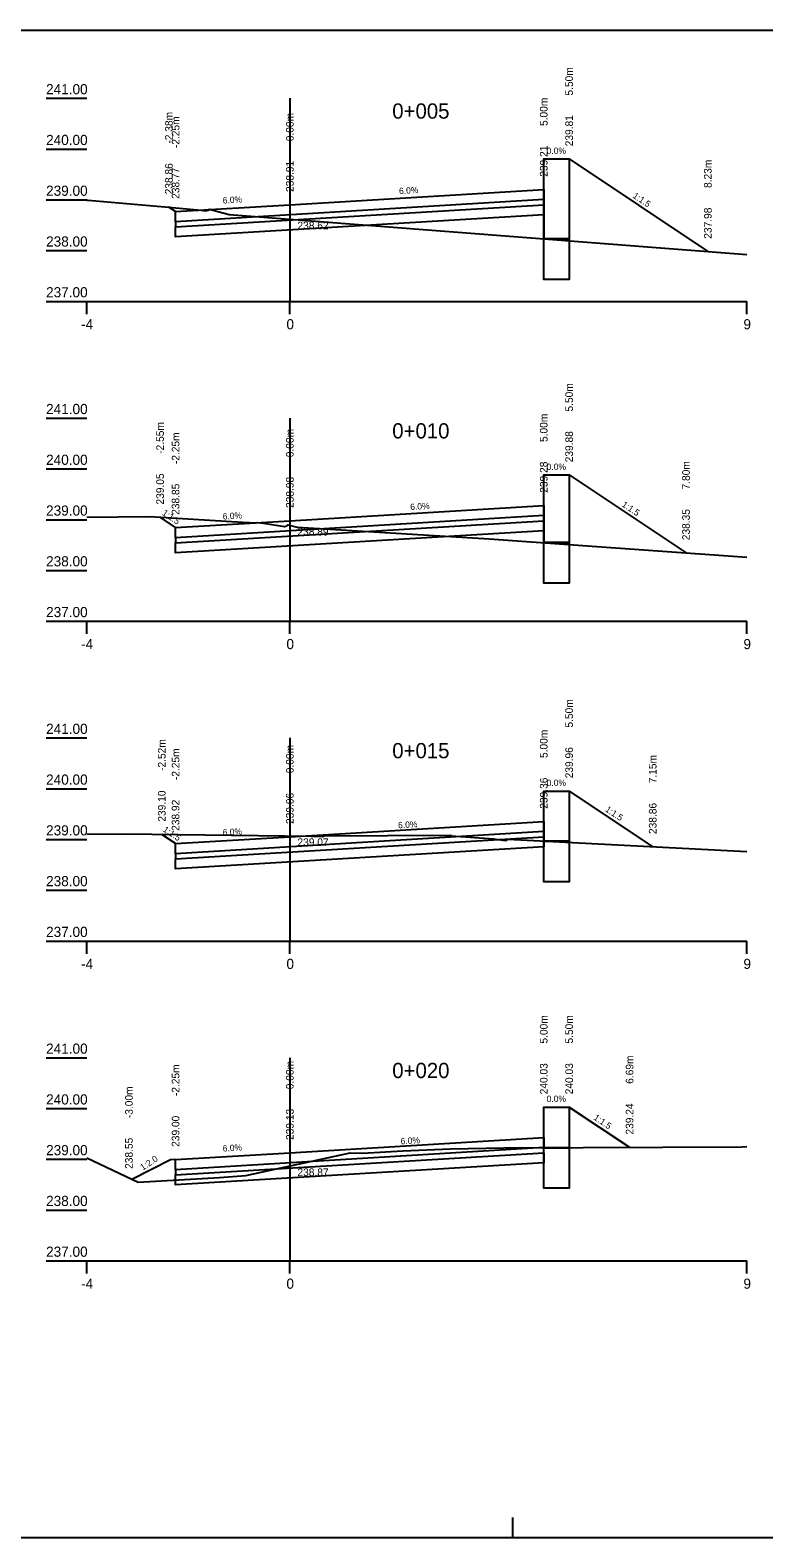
# Model space of a CAD drawing. Extents: x -578374 to -578229, y -1159997 to -1159967.
# Drawn here: x -578259.43 to -578244.98, y -1159996.88 to -1159967.18 of the extents above; entities that cross this region are included whole.
import ezdxf

# ---------------------------------------------------------------- set-up
doc = ezdxf.new("R2010")
doc.units = 0
for name, color, linetype in [('16', 7, 'Continuous'), ('21', 7, 'Continuous'), ('28', 7, 'Continuous'), ('59', 7, 'Continuous'), ('Body pricny rez', 7, 'Continuous'), ('Popis pricneho profilu', 7, 'Continuous'), ('Rámy', 7, 'Continuous')]:
    doc.layers.add(name, color=color, linetype=linetype)

msp = doc.modelspace()

# ---------------------------------------------------------------- linework, layer by layer
for points in [[(-578249.319, -1159970.321), (-578249.319, -1159969.721), (-578248.819, -1159969.721), (-578248.819, -1159971.292), (-578249.319, -1159971.292)], [(-578254.319, -1159970.621), (-578249.319, -1159970.321), (-578249.319, -1159970.521), (-578256.569, -1159970.956), (-578256.569, -1159970.756)], [(-578256.569, -1159970.956), (-578256.569, -1159971.057), (-578249.319, -1159970.622), (-578249.319, -1159970.521)], [(-578249.319, -1159970.622), (-578249.319, -1159970.822), (-578256.569, -1159971.257), (-578256.569, -1159971.057)], [(-578249.319, -1159971.292), (-578248.819, -1159971.292), (-578248.819, -1159972.092), (-578249.319, -1159972.092)], [(-578249.319, -1159976.546), (-578249.319, -1159975.946), (-578248.819, -1159975.946), (-578248.819, -1159977.279), (-578249.319, -1159977.279)], [(-578254.319, -1159976.846), (-578249.319, -1159976.546), (-578249.319, -1159976.746), (-578256.569, -1159977.181), (-578256.569, -1159976.981)], [(-578256.569, -1159977.181), (-578256.569, -1159977.282), (-578249.319, -1159976.847), (-578249.319, -1159976.746)], [(-578249.319, -1159976.847), (-578249.319, -1159977.047), (-578256.569, -1159977.482), (-578256.569, -1159977.282)], [(-578249.319, -1159977.279), (-578248.819, -1159977.279), (-578248.819, -1159978.079), (-578249.319, -1159978.079)], [(-578249.319, -1159982.771), (-578249.319, -1159982.171), (-578248.819, -1159982.171), (-578248.819, -1159983.159), (-578249.319, -1159983.159)], [(-578254.319, -1159983.071), (-578249.319, -1159982.771), (-578249.319, -1159982.971), (-578256.569, -1159983.406), (-578256.569, -1159983.206)], [(-578256.569, -1159983.406), (-578256.569, -1159983.507), (-578249.319, -1159983.072), (-578249.319, -1159982.971)], [(-578249.319, -1159983.072), (-578249.319, -1159983.272), (-578256.569, -1159983.707), (-578256.569, -1159983.507)], [(-578249.319, -1159983.159), (-578248.819, -1159983.159), (-578248.819, -1159983.959), (-578249.319, -1159983.959)], [(-578249.319, -1159988.996), (-578249.319, -1159988.396), (-578248.819, -1159988.396), (-578248.819, -1159989.198), (-578249.319, -1159989.198)], [(-578254.319, -1159989.296), (-578249.319, -1159988.996), (-578249.319, -1159989.196), (-578256.569, -1159989.631), (-578256.569, -1159989.431)], [(-578256.569, -1159989.631), (-578256.569, -1159989.732), (-578249.319, -1159989.297), (-578249.319, -1159989.196)], [(-578249.319, -1159989.297), (-578249.319, -1159989.497), (-578256.569, -1159989.932), (-578256.569, -1159989.732)], [(-578249.319, -1159989.198), (-578248.819, -1159989.198), (-578248.819, -1159989.998), (-578249.319, -1159989.998)]]:
    msp.add_lwpolyline(points, close=True)
for points in [[(-578248.819, -1159969.721), (-578246.088, -1159971.542)], [(-578249.319, -1159970.321), (-578249.319, -1159971.292)], [(-578258.319, -1159970.531), (-578258.289, -1159970.533), (-578256.779, -1159970.661), (-578256.063, -1159970.727), (-578255.975, -1159970.744), (-578255.918, -1159970.727), (-578255.905, -1159970.71), (-578255.515, -1159970.814), (-578245.319, -1159971.601)], [(-578256.569, -1159970.756), (-578256.701, -1159970.668)], [(-578248.819, -1159971.292), (-578248.819, -1159971.292), (-578248.819, -1159971.292), (-578248.819, -1159971.293), (-578248.819, -1159971.292), (-578248.818, -1159971.293), (-578248.819, -1159971.292), (-578248.818, -1159971.292)], [(-578249.319, -1159972.092), (-578249.319, -1159972.092), (-578249.319, -1159972.092), (-578249.319, -1159972.093), (-578249.319, -1159972.092), (-578249.318, -1159972.093), (-578249.319, -1159972.092), (-578249.318, -1159972.092)], [(-578248.819, -1159972.092), (-578248.819, -1159972.092), (-578248.819, -1159972.092), (-578248.819, -1159972.093), (-578248.819, -1159972.092), (-578248.818, -1159972.093), (-578248.819, -1159972.092), (-578248.818, -1159972.092)], [(-578248.819, -1159975.946), (-578246.517, -1159977.481)], [(-578249.319, -1159976.546), (-578249.319, -1159977.279)], [(-578258.319, -1159976.774), (-578257.073, -1159976.766), (-578255.248, -1159976.875), (-578254.979, -1159976.889), (-578254.955, -1159976.881), (-578254.838, -1159976.893), (-578254.424, -1159976.962), (-578254.379, -1159976.949), (-578254.36, -1159976.928), (-578254.177, -1159976.971), (-578250.394, -1159977.201), (-578245.319, -1159977.567)], [(-578256.569, -1159976.981), (-578256.874, -1159976.778)], [(-578248.819, -1159977.279), (-578248.819, -1159977.278), (-578248.819, -1159977.279), (-578248.819, -1159977.279), (-578248.819, -1159977.279), (-578248.818, -1159977.279), (-578248.819, -1159977.279), (-578248.818, -1159977.278)], [(-578249.319, -1159978.079), (-578249.319, -1159978.078), (-578249.319, -1159978.079), (-578249.319, -1159978.079), (-578249.319, -1159978.079), (-578249.318, -1159978.079), (-578249.319, -1159978.079), (-578249.318, -1159978.078)], [(-578248.819, -1159978.079), (-578248.819, -1159978.078), (-578248.819, -1159978.079), (-578248.819, -1159978.079), (-578248.819, -1159978.079), (-578248.818, -1159978.079), (-578248.819, -1159978.079), (-578248.818, -1159978.078)], [(-578248.819, -1159982.171), (-578247.173, -1159983.269)], [(-578249.319, -1159982.771), (-578249.319, -1159983.159)], [(-578258.319, -1159983.02), (-578257.562, -1159983.017), (-578253.899, -1159983.059), (-578253.681, -1159983.068), (-578253.644, -1159983.056), (-578253.643, -1159983.052), (-578251.151, -1159983.039), (-578251.14, -1159983.056), (-578250.299, -1159983.115), (-578250.069, -1159983.143), (-578250.044, -1159983.138), (-578250.027, -1159983.123), (-578245.319, -1159983.363)], [(-578256.569, -1159983.206), (-578256.841, -1159983.025)], [(-578248.819, -1159983.159), (-578248.819, -1159983.159), (-578248.819, -1159983.159), (-578248.819, -1159983.16), (-578248.819, -1159983.159), (-578248.818, -1159983.16), (-578248.819, -1159983.159), (-578248.818, -1159983.159)], [(-578249.319, -1159983.959), (-578249.319, -1159983.959), (-578249.319, -1159983.959), (-578249.319, -1159983.96), (-578249.319, -1159983.959), (-578249.318, -1159983.96), (-578249.319, -1159983.959), (-578249.318, -1159983.959)], [(-578248.819, -1159983.959), (-578248.819, -1159983.959), (-578248.819, -1159983.959), (-578248.819, -1159983.96), (-578248.819, -1159983.959), (-578248.818, -1159983.96), (-578248.819, -1159983.959), (-578248.818, -1159983.959)], [(-578248.819, -1159988.396), (-578247.629, -1159989.189)], [(-578249.319, -1159988.996), (-578249.319, -1159989.198)], [(-578258.319, -1159989.395), (-578257.309, -1159989.879), (-578255.701, -1159989.784), (-578255.188, -1159989.747), (-578253.132, -1159989.296), (-578252.889, -1159989.302), (-578252.095, -1159989.261), (-578251.158, -1159989.222), (-578250.106, -1159989.201), (-578245.411, -1159989.178), (-578245.319, -1159989.173)], [(-578248.819, -1159989.198), (-578248.819, -1159989.197), (-578248.819, -1159989.198), (-578248.819, -1159989.198), (-578248.819, -1159989.198), (-578248.818, -1159989.198), (-578248.819, -1159989.198), (-578248.818, -1159989.197)], [(-578256.569, -1159989.431), (-578256.669, -1159989.439), (-578257.432, -1159989.821)], [(-578249.319, -1159989.998), (-578249.319, -1159989.997), (-578249.319, -1159989.998), (-578249.319, -1159989.998), (-578249.319, -1159989.998), (-578249.318, -1159989.998), (-578249.319, -1159989.998), (-578249.318, -1159989.997)], [(-578248.819, -1159989.998), (-578248.819, -1159989.997), (-578248.819, -1159989.998), (-578248.819, -1159989.998), (-578248.819, -1159989.998), (-578248.818, -1159989.998), (-578248.819, -1159989.998), (-578248.818, -1159989.997)]]:
    msp.add_lwpolyline(points)
at = {"layer": '16'}
for p, q in [((-578258.319, -1159972.526), (-578245.319, -1159972.526)), ((-578258.319, -1159978.826), (-578245.319, -1159978.826)), ((-578258.319, -1159985.126), (-578245.319, -1159985.126)), ((-578258.319, -1159991.426), (-578245.319, -1159991.426))]:
    msp.add_line(p, q, dxfattribs=at)
at = {"layer": '21'}
for p, q in [((-578259.119, -1159968.526), (-578258.319, -1159968.526)), ((-578259.119, -1159969.526), (-578258.319, -1159969.526)), ((-578259.119, -1159970.526), (-578258.319, -1159970.526)), ((-578259.119, -1159971.526), (-578258.319, -1159971.526)), ((-578259.119, -1159972.526), (-578258.319, -1159972.526)), ((-578259.119, -1159974.826), (-578258.319, -1159974.826)), ((-578259.119, -1159975.826), (-578258.319, -1159975.826)), ((-578259.119, -1159976.826), (-578258.319, -1159976.826)), ((-578259.119, -1159977.826), (-578258.319, -1159977.826)), ((-578259.119, -1159978.826), (-578258.319, -1159978.826)), ((-578259.119, -1159981.126), (-578258.319, -1159981.126)), ((-578259.119, -1159982.126), (-578258.319, -1159982.126)), ((-578259.119, -1159983.126), (-578258.319, -1159983.126)), ((-578259.119, -1159984.126), (-578258.319, -1159984.126)), ((-578259.119, -1159985.126), (-578258.319, -1159985.126)), ((-578259.119, -1159987.426), (-578258.319, -1159987.426)), ((-578259.119, -1159988.426), (-578258.319, -1159988.426)), ((-578259.119, -1159989.426), (-578258.319, -1159989.426)), ((-578259.119, -1159990.426), (-578258.319, -1159990.426)), ((-578259.119, -1159991.426), (-578258.319, -1159991.426))]:
    msp.add_line(p, q, dxfattribs=at)
at = {"layer": '28'}
for p, q in [((-578254.319, -1159968.526), (-578254.319, -1159972.526)), ((-578254.319, -1159974.826), (-578254.319, -1159978.826)), ((-578254.319, -1159981.126), (-578254.319, -1159985.126)), ((-578254.319, -1159987.426), (-578254.319, -1159991.426))]:
    msp.add_line(p, q, dxfattribs=at)
at = {"layer": '59'}
for p, q in [((-578258.319, -1159972.776), (-578258.319, -1159972.526)), ((-578254.319, -1159972.776), (-578254.319, -1159972.526)), ((-578245.319, -1159972.776), (-578245.319, -1159972.526)), ((-578258.319, -1159979.076), (-578258.319, -1159978.826)), ((-578254.319, -1159979.076), (-578254.319, -1159978.826)), ((-578245.319, -1159979.076), (-578245.319, -1159978.826)), ((-578258.319, -1159985.376), (-578258.319, -1159985.126)), ((-578254.319, -1159985.376), (-578254.319, -1159985.126)), ((-578245.319, -1159985.376), (-578245.319, -1159985.126)), ((-578258.319, -1159991.676), (-578258.319, -1159991.426)), ((-578254.319, -1159991.676), (-578254.319, -1159991.426)), ((-578245.319, -1159991.676), (-578245.319, -1159991.426))]:
    msp.add_line(p, q, dxfattribs=at)
at = {"layer": 'Rámy'}
msp.add_line((-578249.93, -1159996.883), (-578249.93, -1159996.483), dxfattribs=at)
msp.add_lwpolyline([(-578373.807, -1159967.183), (-578228.93, -1159967.183), (-578228.93, -1159996.883), (-578373.807, -1159996.883)], close=True, dxfattribs=at)

# ---------------------------------------------------------------- texts
for s, p in [('0+005', (-578252.302, -1159968.926)), ('0+010', (-578252.302, -1159975.226)), ('0+015', (-578252.302, -1159981.526)), ('0+020', (-578252.302, -1159987.826))]:
    msp.add_text(s, height=0.3).set_placement(p)
for s, rotation, p in [('1:1.5', 326.3099, (-578247.577, -1159970.474)), ('1:1.5', 326.3099, (-578247.792, -1159976.556)), ('1:1.5', 326.3098, (-578256.845, -1159976.722)), ('1:1.5', 326.3099, (-578248.12, -1159982.562)), ('1:1.5', 326.3098, (-578256.829, -1159982.958)), ('1:1.5', 326.3099, (-578248.348, -1159988.635)), ('1:2.0', 33.6901, (-578257.214, -1159989.653))]:
    msp.add_text(s, height=0.125, rotation=rotation).set_placement(p)
at = {"layer": '16'}
for s, rotation, p in [('0.0%', 360, (-578249.262, -1159969.621)), ('6.0%', 3.4336, (-578252.165, -1159970.415)), ('6.0%', 3.4336, (-578255.637, -1159970.6)), ('0.0%', 360, (-578249.262, -1159975.846)), ('6.0%', 3.4336, (-578251.945, -1159976.637)), ('6.0%', 3.4336, (-578255.637, -1159976.825)), ('0.0%', 360, (-578249.262, -1159982.071)), ('6.0%', 3.4336, (-578252.184, -1159982.907)), ('6.0%', 3.4336, (-578255.637, -1159983.05)), ('0.0%', 360, (-578249.262, -1159988.296)), ('6.0%', 3.4336, (-578252.134, -1159989.132)), ('6.0%', 3.4336, (-578255.637, -1159989.275))]:
    msp.add_text(s, height=0.125, rotation=rotation, dxfattribs=at).set_placement(p)
at = {"layer": '21'}
for s, p in [('241.00', (-578259.119, -1159968.446)), ('240.00', (-578259.119, -1159969.446)), ('239.00', (-578259.119, -1159970.446)), ('238.00', (-578259.119, -1159971.446)), ('237.00', (-578259.119, -1159972.446)), ('-4', (-578258.429, -1159973.076)), ('0', (-578254.386, -1159973.076)), ('9', (-578245.386, -1159973.076)), ('241.00', (-578259.119, -1159974.746)), ('240.00', (-578259.119, -1159975.746)), ('239.00', (-578259.119, -1159976.746)), ('238.00', (-578259.119, -1159977.746)), ('237.00', (-578259.119, -1159978.746)), ('-4', (-578258.429, -1159979.376)), ('0', (-578254.386, -1159979.376)), ('9', (-578245.386, -1159979.376)), ('241.00', (-578259.119, -1159981.046)), ('240.00', (-578259.119, -1159982.046)), ('239.00', (-578259.119, -1159983.046)), ('238.00', (-578259.119, -1159984.046)), ('237.00', (-578259.119, -1159985.046)), ('0', (-578254.386, -1159985.676)), ('9', (-578245.386, -1159985.676)), ('-4', (-578258.429, -1159985.676)), ('241.00', (-578259.119, -1159987.346)), ('240.00', (-578259.119, -1159988.346)), ('239.00', (-578259.119, -1159989.346)), ('238.00', (-578259.119, -1159990.346)), ('237.00', (-578259.119, -1159991.346)), ('-4', (-578258.429, -1159991.976)), ('0', (-578254.386, -1159991.976)), ('9', (-578245.386, -1159991.976))]:
    msp.add_text(s, height=0.2, dxfattribs=at).set_placement(p)
at = {"layer": '59'}
for s, p in [('238.62', (-578254.169, -1159971.106)), ('238.89', (-578254.169, -1159977.138)), ('239.07', (-578254.169, -1159983.254)), ('238.87', (-578254.169, -1159989.756))]:
    msp.add_text(s, height=0.15, dxfattribs=at).set_placement(p)
at = {"layer": 'Body pricny rez'}
for p in [(-578249.319, -1159969.722), (-578248.819, -1159969.722), (-578249.319, -1159970.322), (-578254.319, -1159970.622), (-578256.701, -1159970.669), (-578256.569, -1159970.757), (-578246.088, -1159971.543), (-578249.319, -1159975.947), (-578248.819, -1159975.947), (-578249.319, -1159976.547), (-578256.874, -1159976.778), (-578254.319, -1159976.847), (-578256.569, -1159976.982), (-578246.517, -1159977.482), (-578249.319, -1159982.172), (-578248.819, -1159982.172), (-578249.319, -1159982.772), (-578256.841, -1159983.025), (-578254.319, -1159983.072), (-578256.569, -1159983.207), (-578247.173, -1159983.269), (-578249.319, -1159988.397), (-578248.819, -1159988.397), (-578249.319, -1159988.997), (-578254.319, -1159989.297), (-578247.63, -1159989.19), (-578256.669, -1159989.44), (-578256.569, -1159989.432), (-578257.322, -1159989.874)]:
    msp.add_text('+', height=0.001, dxfattribs=at).set_placement(p)
at = {"layer": 'Popis pricneho profilu'}
for s, p in [('5.50m', (-578248.744, -1159968.471)), ('5.00m', (-578249.244, -1159969.071)), ('-2.38m', (-578256.626, -1159969.418)), ('0.00m', (-578254.244, -1159969.371)), ('-2.25m', (-578256.494, -1159969.506)), ('239.81', (-578248.744, -1159969.471)), ('239.21', (-578249.244, -1159970.071)), ('238.86', (-578256.626, -1159970.418)), ('238.77', (-578256.494, -1159970.506)), ('238.91', (-578254.244, -1159970.371)), ('8.23m', (-578246.013, -1159970.292)), ('237.98', (-578246.013, -1159971.292)), ('5.50m', (-578248.744, -1159974.696)), ('5.00m', (-578249.244, -1159975.296)), ('-2.55m', (-578256.799, -1159975.528)), ('0.00m', (-578254.244, -1159975.596)), ('-2.25m', (-578256.494, -1159975.731)), ('239.88', (-578248.744, -1159975.696)), ('239.05', (-578256.799, -1159976.528)), ('239.28', (-578249.244, -1159976.296)), ('7.80m', (-578246.442, -1159976.231)), ('238.85', (-578256.494, -1159976.731)), ('238.98', (-578254.244, -1159976.596)), ('238.35', (-578246.442, -1159977.231)), ('5.50m', (-578248.744, -1159980.921)), ('5.00m', (-578249.244, -1159981.521)), ('-2.52m', (-578256.766, -1159981.775)), ('0.00m', (-578254.244, -1159981.821)), ('239.96', (-578248.744, -1159981.921)), ('-2.25m', (-578256.494, -1159981.956)), ('7.15m', (-578247.098, -1159982.019)), ('239.10', (-578256.766, -1159982.775)), ('239.36', (-578249.244, -1159982.521)), ('238.92', (-578256.494, -1159982.956)), ('239.06', (-578254.244, -1159982.821)), ('238.86', (-578247.098, -1159983.019)), ('5.00m', (-578249.244, -1159987.146)), ('5.50m', (-578248.744, -1159987.146)), ('0.00m', (-578254.244, -1159988.046)), ('240.03', (-578249.244, -1159988.146)), ('240.03', (-578248.744, -1159988.146)), ('6.69m', (-578247.554, -1159987.939)), ('-2.25m', (-578256.494, -1159988.181)), ('-3.00m', (-578257.413, -1159988.615)), ('239.13', (-578254.244, -1159989.046)), ('239.24', (-578247.554, -1159988.939)), ('239.00', (-578256.494, -1159989.181)), ('238.55', (-578257.413, -1159989.615))]:
    msp.add_text(s, height=0.15, rotation=90, dxfattribs=at).set_placement(p)

doc.saveas('drawing.dxf')
